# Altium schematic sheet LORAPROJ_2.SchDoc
size A; SheetNumber: 2; SheetTotal: 3
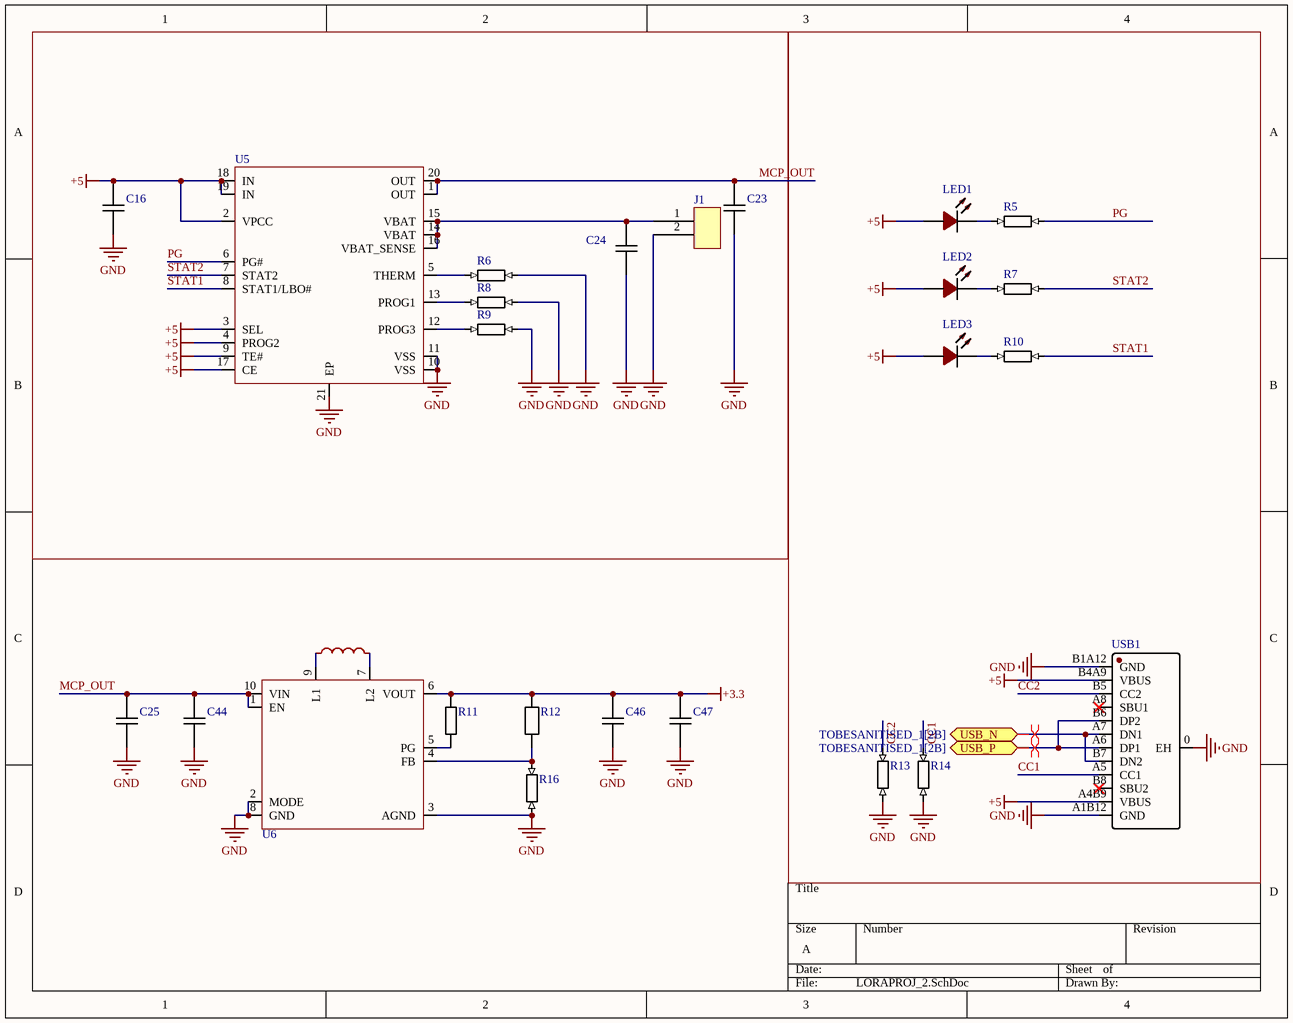
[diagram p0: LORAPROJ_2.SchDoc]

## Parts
C16  (no value)  [CAP_0603]
C23  (no value)  [CAP_0603]
C24  (no value)  [CAP_0603]
C25  (no value)  [CAP_0603]
C44  (no value)  [CAP_0603]
C46  (no value)  [CAP_0603]
C47  (no value)  [CAP_0603]
J1  (no value)  [2.0 2P-Footprint-1]
L14  (no value)  [Inductor]
LED1  (no value)  [LED_0603]
LED2  (no value)  [LED_0603]
LED3  (no value)  [LED_0603]
R5  (no value)  [RES_0603]
R6  (no value)  [RES_0603]
R7  (no value)  [RES_0603]
R8  (no value)  [RES_0603]
R9  (no value)  [RES_0603]
R10  (no value)  [RES_0603]
R11  (no value)  [RES_0603]
R12  (no value)  [RES_0603]
R13  (no value)  [RES_0603]
R14  (no value)  [RES_0603]
R16  (no value)  [RES_0603]
U5  (no value)  [QFN-20_4x4_P0.5_EP]
U6  (no value)  [VSON-10_3x2_P0.5]
USB1  (no value)  [USB-C_SMD_16P]

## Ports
USB_N (bidir, see TOBESANITISED_1[2B]), USB_P (bidir, see TOBESANITISED_1[2B])

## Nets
+3.3: C46.2 C47.2 R11.2 R12.2 U6.6(VOUT)
+5: C16.2 LED1.2(A) LED2.2(A) LED3.2(A) U5.2(VPCC) U5.3(SEL) U5.4(PROG2) U5.9(TE#) U5.17(CE) U5.18(IN) U5.19(IN) USB1.A4B9(VBUS) USB1.B4A9(VBUS)
GND: C16.1 C23.1 C24.1 C25.1 C44.1 C46.1 C47.1 J1.2 R6.2 R8.2 R9.2 R13.1 R14.1 R16.1 U5.10(VSS) U5.11(VSS) U5.21(EP) U6.2(MODE) U6.3(AGND) U6.8(GND) USB1.0(EH) USB1.A1B12(GND) USB1.B1A12(GND)
CC1: R14.2 USB1.A5(CC1)
CC2: R13.2 USB1.B5(CC2)
MCP_OUT: C23.2 C25.2 C44.2 U5.1(OUT) U5.20(OUT) U6.1(EN) U6.10(VIN)
PG: R5.2 U5.6(PG#)
STAT1: R10.2 U5.8(STAT1/LBO#)
STAT2: R7.2 U5.7(STAT2)
USB_N: USB1.A7(DN1) USB1.B7(DN2) ; port USB_N
USB_P: USB1.A6(DP1) USB1.B6(DP2) ; port USB_P
NetC24_2: C24.2 J1.1 U5.14(VBAT) U5.15(VBAT) U5.16(VBAT_SENSE)
NetL14_1: L14.1 U6.9(L1)
NetL14_2: L14.2 U6.7(L2)
NetLED1_1: LED1.1(C) R5.1
NetLED2_1: LED2.1(C) R7.1
NetLED3_1: LED3.1(C) R10.1
NetR6_1: R6.1 U5.5(THERM)
NetR8_1: R8.1 U5.13(PROG1)
NetR9_1: R9.1 U5.12(PROG3)
NetR11_1: R11.1 U6.5(PG)
NetR12_1: R12.1 R16.2 U6.4(FB)

Not connected (* = marked no-connect by the designer): USB1 A8(SBU1)* B8(SBU2)*

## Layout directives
differential pair: USB_N, USB_P

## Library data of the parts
C16 C23-C25 C44 C46 C47 = CAP
J1 = CONN
L14 = IND: AddInBom: yes
LED1-LED3 = LED
R5-R14 R16 = RES
U5 = IC_U5
U6 = IC_U6
USB1 = CONN_USB_C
